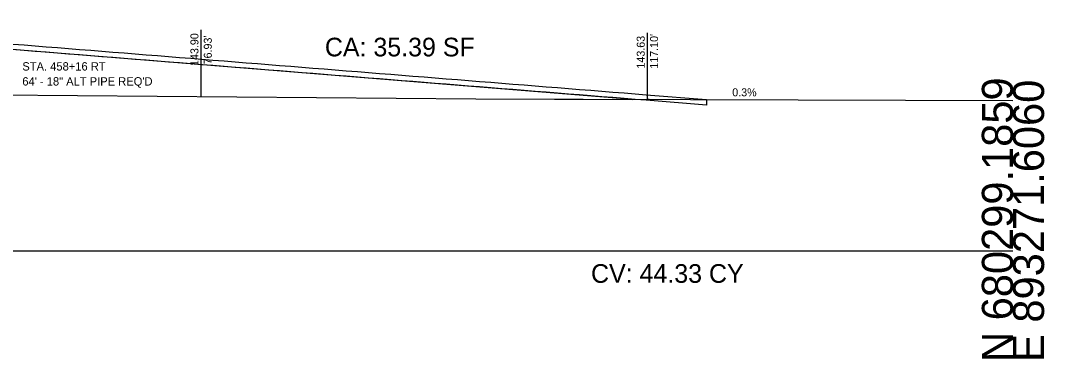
# Model space of a CAD drawing. Extents: x -26 to 4303, y -13 to 10775.
# Drawn here: x 210.7 to 302.8, y 6490.3 to 6520.7 of the extents above; entities that cross this region are included whole.
import ezdxf

# ---------------------------------------------------------------- set-up
doc = ezdxf.new("R2010")
doc.units = 0
for name, color, linetype in [('DTM_P_FINISHED_GRADE', 7, 'Continuous'), ('DTM_X_GROUND', 7, 'Continuous'), ('X_PROFILES_1', 7, 'Continuous'), ('XS_CELL', 7, 'Continuous'), ('XS_M_SHAPES_EARTHWORK', 7, 'Continuous'), ('XS_P_DR_GRAVEL', 7, 'Continuous'), ('XS_P_DRAINAGE', 7, 'Continuous'), ('XS_P_GROUND', 7, 'Continuous'), ('XS_P_TX_CLEARZONE', 7, 'Continuous'), ('XS_P_TX_FS_BS', 7, 'Continuous'), ('XS_SHEET_EW_TX_AREA', 7, 'Continuous'), ('XS_SHEET_EW_TX_VOLUME', 7, 'Continuous')]:
    doc.layers.add(name, color=color, linetype=linetype)

msp = doc.modelspace()

# ---------------------------------------------------------------- linework, layer by layer
at = {"layer": 'DTM_P_FINISHED_GRADE'}
for p, q in [((210, 6518.61), (211, 6518.53)), ((211, 6518.53), (212, 6518.45)), ((212, 6518.45), (213, 6518.37)), ((213, 6518.37), (214, 6518.29)), ((214, 6518.29), (215, 6518.21)), ((215, 6518.21), (216, 6518.13)), ((216, 6518.13), (217, 6518.05)), ((217, 6518.05), (218, 6517.97)), ((218, 6517.97), (219, 6517.89)), ((219, 6517.89), (220, 6517.81)), ((220, 6517.81), (221, 6517.73)), ((221, 6517.73), (222, 6517.65)), ((222, 6517.65), (223, 6517.57)), ((223, 6517.57), (224, 6517.49)), ((224, 6517.49), (225, 6517.41)), ((225, 6517.41), (226, 6517.33)), ((226, 6517.33), (227, 6517.25)), ((227, 6517.25), (228, 6517.17)), ((228, 6517.17), (229, 6517.09)), ((229, 6517.09), (230, 6517.01)), ((230, 6517.01), (231, 6516.93)), ((231, 6516.93), (232, 6516.85)), ((232, 6516.85), (233, 6516.77)), ((233, 6516.77), (234, 6516.69)), ((234, 6516.69), (235, 6516.61)), ((235, 6516.61), (236, 6516.53)), ((236, 6516.53), (237, 6516.45)), ((237, 6516.45), (238, 6516.37)), ((238, 6516.37), (239, 6516.29)), ((239, 6516.29), (240, 6516.21)), ((240, 6516.21), (241, 6516.13)), ((241, 6516.13), (242, 6516.05)), ((242, 6516.05), (243, 6515.97)), ((243, 6515.97), (244, 6515.89)), ((244, 6515.89), (245, 6515.81)), ((245, 6515.81), (246, 6515.73)), ((246, 6515.73), (247, 6515.65)), ((247, 6515.65), (248, 6515.57)), ((248, 6515.57), (249, 6515.49)), ((249, 6515.49), (250, 6515.41)), ((250, 6515.41), (251, 6515.33)), ((251, 6515.33), (252, 6515.25)), ((252, 6515.25), (253, 6515.17)), ((253, 6515.17), (254, 6515.09)), ((254, 6515.09), (255, 6515.01)), ((255, 6515.01), (256, 6514.93)), ((256, 6514.93), (257, 6514.85)), ((257, 6514.85), (258, 6514.77)), ((258, 6514.77), (259, 6514.69)), ((259, 6514.69), (260, 6514.61)), ((260, 6514.61), (261, 6514.53)), ((261, 6514.53), (262, 6514.45)), ((262, 6514.45), (263, 6514.37)), ((263, 6514.37), (264, 6514.29)), ((264, 6514.29), (265, 6514.21)), ((265, 6514.21), (266, 6514.13)), ((266, 6514.13), (267, 6514.05)), ((267, 6514.05), (272.418, 6513.617))]:
    msp.add_line(p, q, dxfattribs=at)
at = {"layer": 'DTM_X_GROUND'}
msp.add_lwpolyline([(105.463, 6520.066), (110.938, 6519.731), (112.559, 6519.617), (118.219, 6519.184), (128.479, 6518.403), (133.698, 6517.87), (147.015, 6515.451), (147.695, 6515.138), (149.956, 6514.928), (150.417, 6514.984), (154.047, 6515.295), (164.928, 6514.685), (174.961, 6514.311), (196.656, 6514.261), (208.614, 6514.054), (251.671, 6513.687), (300, 6513.523)], dxfattribs=at)
at = {"layer": 'XS_CELL'}
msp.add_line((150, 6500), (300, 6500), dxfattribs=at)
at = {"layer": 'XS_P_DR_GRAVEL'}
for p, q in [((210, 6518.61), (211, 6518.53)), ((211, 6518.03), (210, 6518.11)), ((211, 6518.53), (212, 6518.45)), ((212, 6517.95), (211, 6518.03)), ((212, 6518.45), (213, 6518.37)), ((213, 6517.87), (212, 6517.95)), ((213, 6518.37), (214, 6518.29)), ((214, 6517.79), (213, 6517.87)), ((214, 6518.29), (215, 6518.21)), ((215, 6517.71), (214, 6517.79)), ((215, 6518.21), (216, 6518.13)), ((216, 6518.13), (217, 6518.05)), ((217, 6518.05), (218, 6517.97)), ((218, 6517.97), (219, 6517.89)), ((219, 6517.89), (220, 6517.81)), ((220, 6517.81), (221, 6517.73)), ((216, 6517.63), (215, 6517.71)), ((217, 6517.55), (216, 6517.63)), ((218, 6517.47), (217, 6517.55)), ((219, 6517.39), (218, 6517.47)), ((220, 6517.31), (219, 6517.39)), ((221, 6517.23), (220, 6517.31)), ((221, 6517.73), (222, 6517.65)), ((222, 6517.15), (221, 6517.23)), ((222, 6517.65), (223, 6517.57)), ((223, 6517.07), (222, 6517.15)), ((223, 6517.57), (224, 6517.49)), ((224, 6516.99), (223, 6517.07)), ((224, 6517.49), (225, 6517.41)), ((225, 6516.91), (224, 6516.99)), ((225, 6517.41), (226, 6517.33)), ((226, 6516.83), (225, 6516.91)), ((226, 6517.33), (227, 6517.25)), ((227, 6517.25), (228, 6517.17)), ((228, 6517.17), (229, 6517.09)), ((229, 6517.09), (230, 6517.01)), ((230, 6517.01), (231, 6516.93)), ((231, 6516.93), (232, 6516.85)), ((232, 6516.85), (233, 6516.77)), ((227, 6516.75), (226, 6516.83)), ((228, 6516.67), (227, 6516.75)), ((229, 6516.59), (228, 6516.67)), ((230, 6516.51), (229, 6516.59)), ((231, 6516.43), (230, 6516.51)), ((232, 6516.35), (231, 6516.43)), ((233, 6516.27), (232, 6516.35)), ((233, 6516.77), (234, 6516.69)), ((234, 6516.19), (233, 6516.27)), ((234, 6516.69), (235, 6516.61)), ((235, 6516.11), (234, 6516.19)), ((235, 6516.61), (236, 6516.53)), ((236, 6516.03), (235, 6516.11)), ((236, 6516.53), (237, 6516.45)), ((237, 6515.95), (236, 6516.03)), ((237, 6516.45), (238, 6516.37)), ((238, 6515.87), (237, 6515.95)), ((238, 6516.37), (239, 6516.29)), ((239, 6516.29), (240, 6516.21)), ((240, 6516.21), (241, 6516.13)), ((241, 6516.13), (242, 6516.05)), ((242, 6516.05), (243, 6515.97)), ((243, 6515.97), (244, 6515.89)), ((239, 6515.79), (238, 6515.87)), ((240, 6515.71), (239, 6515.79)), ((241, 6515.63), (240, 6515.71)), ((242, 6515.55), (241, 6515.63)), ((243, 6515.47), (242, 6515.55)), ((244, 6515.39), (243, 6515.47)), ((244, 6515.89), (245, 6515.81)), ((245, 6515.31), (244, 6515.39)), ((245, 6515.81), (246, 6515.73)), ((246, 6515.23), (245, 6515.31)), ((246, 6515.73), (247, 6515.65)), ((247, 6515.15), (246, 6515.23)), ((247, 6515.65), (248, 6515.57)), ((248, 6515.07), (247, 6515.15)), ((248, 6515.57), (249, 6515.49)), ((249, 6514.99), (248, 6515.07)), ((249, 6515.49), (250, 6515.41)), ((250, 6515.41), (251, 6515.33)), ((251, 6515.33), (252, 6515.25)), ((252, 6515.25), (253, 6515.17)), ((253, 6515.17), (254, 6515.09)), ((254, 6515.09), (255, 6515.01)), ((255, 6515.01), (256, 6514.93)), ((250, 6514.91), (249, 6514.99)), ((251, 6514.83), (250, 6514.91)), ((252, 6514.75), (251, 6514.83)), ((253, 6514.67), (252, 6514.75)), ((254, 6514.59), (253, 6514.67)), ((255, 6514.51), (254, 6514.59)), ((256, 6514.43), (255, 6514.51)), ((256, 6514.93), (257, 6514.85)), ((257, 6514.35), (256, 6514.43)), ((257, 6514.85), (258, 6514.77)), ((258, 6514.27), (257, 6514.35)), ((258, 6514.77), (259, 6514.69)), ((259, 6514.19), (258, 6514.27)), ((259, 6514.69), (260, 6514.61)), ((260, 6514.11), (259, 6514.19)), ((260, 6514.61), (261, 6514.53)), ((261, 6514.03), (260, 6514.11)), ((261, 6514.53), (262, 6514.45)), ((262, 6514.45), (263, 6514.37)), ((263, 6514.37), (264, 6514.29)), ((264, 6514.29), (265, 6514.21)), ((265, 6514.21), (266, 6514.13)), ((266, 6514.13), (267, 6514.05)), ((262, 6513.95), (261, 6514.03)), ((263, 6513.87), (262, 6513.95)), ((264, 6513.79), (263, 6513.87)), ((265, 6513.71), (264, 6513.79)), ((266, 6513.63), (265, 6513.71)), ((267, 6513.55), (266, 6513.63)), ((267, 6514.05), (272.418, 6513.617)), ((272.418, 6513.117), (267, 6513.55)), ((272.418, 6513.617), (272.418, 6513.117))]:
    msp.add_line(p, q, dxfattribs=at)
at = {"layer": 'XS_P_GROUND'}
msp.add_lwpolyline([(267.098, 6513.635), (267.265, 6513.622)], dxfattribs=at)
at = {"layer": 'XS_P_TX_CLEARZONE'}
for p, q in [((226.933, 6513.898), (226.933, 6519.898)), ((226.933, 6513.898), (226.933, 6519.898)), ((226.933, 6513.898), (226.933, 6519.898)), ((267.098, 6513.635), (267.098, 6519.635)), ((267.098, 6513.635), (267.098, 6519.635)), ((267.098, 6513.635), (267.098, 6519.635))]:
    msp.add_line(p, q, dxfattribs=at)
at = {"layer": 'XS_SHEET_EW_TX_AREA'}
for points in [[(170.274, 6520.732), (180, 6518.274), (192.007, 6514.272), (208.614, 6514.054), (230.143, 6513.87), (251.671, 6513.687), (265.777, 6513.629), (239, 6515.79), (214, 6517.79), (193, 6519.47), (182, 6520.35), (180, 6520.51), (177, 6520.576), (172.5, 6520.675)], [(267.098, 6513.635), (267.265, 6513.634), (267.265, 6513.622)]]:
    msp.add_lwpolyline(points, close=True, dxfattribs=at)

# ---------------------------------------------------------------- texts
at = {"layer": 'X_PROFILES_1'}
for p in [(226.893, 6513.838), (267.059, 6513.575)]:
    msp.add_text('X', height=0.12, dxfattribs=at).set_placement(p)
at = {"layer": 'XS_CELL'}
for s, p in [('N 680299.1859', (300, 6490)), ('E 893271.6060', (302.8, 6490))]:
    msp.add_text(s, height=2.8, rotation=90, dxfattribs=at).set_placement(p)
at = {"layer": 'XS_M_SHAPES_EARTHWORK'}
msp.add_text('CV: 44.33 CY', height=1.68, dxfattribs=at).set_placement((262.026, 6497.12))
at = {"layer": 'XS_P_DRAINAGE'}
for s, p in [('STA. 458+16 RT', (210.842, 6516.227)), ('64\' - 18" ALT PIPE REQ\'D', (210.842, 6514.877))]:
    msp.add_text(s, height=0.75, dxfattribs=at).set_placement(p)
at = {"layer": 'XS_P_TX_CLEARZONE'}
for s, p in [('143.90', (226.693, 6516.639)), ('143.90', (226.693, 6516.639)), ('143.90', (226.693, 6516.639)), ("76.93'", (227.893, 6516.781)), ("76.93'", (227.893, 6516.781)), ("76.93'", (227.893, 6516.781)), ('143.63', (266.858, 6516.405)), ('143.63', (266.858, 6516.405)), ('143.63', (266.858, 6516.405)), ("117.10'", (268.058, 6516.393)), ("117.10'", (268.058, 6516.393)), ("117.10'", (268.058, 6516.393))]:
    msp.add_text(s, height=0.72, rotation=90, dxfattribs=at).set_placement(p)
at = {"layer": 'XS_P_TX_FS_BS'}
msp.add_text('0.3%', height=0.72, rotation=359.80641, dxfattribs=at).set_placement((274.735, 6513.909))
at = {"layer": 'XS_SHEET_EW_TX_VOLUME'}
msp.add_text('CA: 35.39 SF', height=1.68, dxfattribs=at).set_placement((238.072, 6517.5))

doc.saveas('drawing.dxf')
